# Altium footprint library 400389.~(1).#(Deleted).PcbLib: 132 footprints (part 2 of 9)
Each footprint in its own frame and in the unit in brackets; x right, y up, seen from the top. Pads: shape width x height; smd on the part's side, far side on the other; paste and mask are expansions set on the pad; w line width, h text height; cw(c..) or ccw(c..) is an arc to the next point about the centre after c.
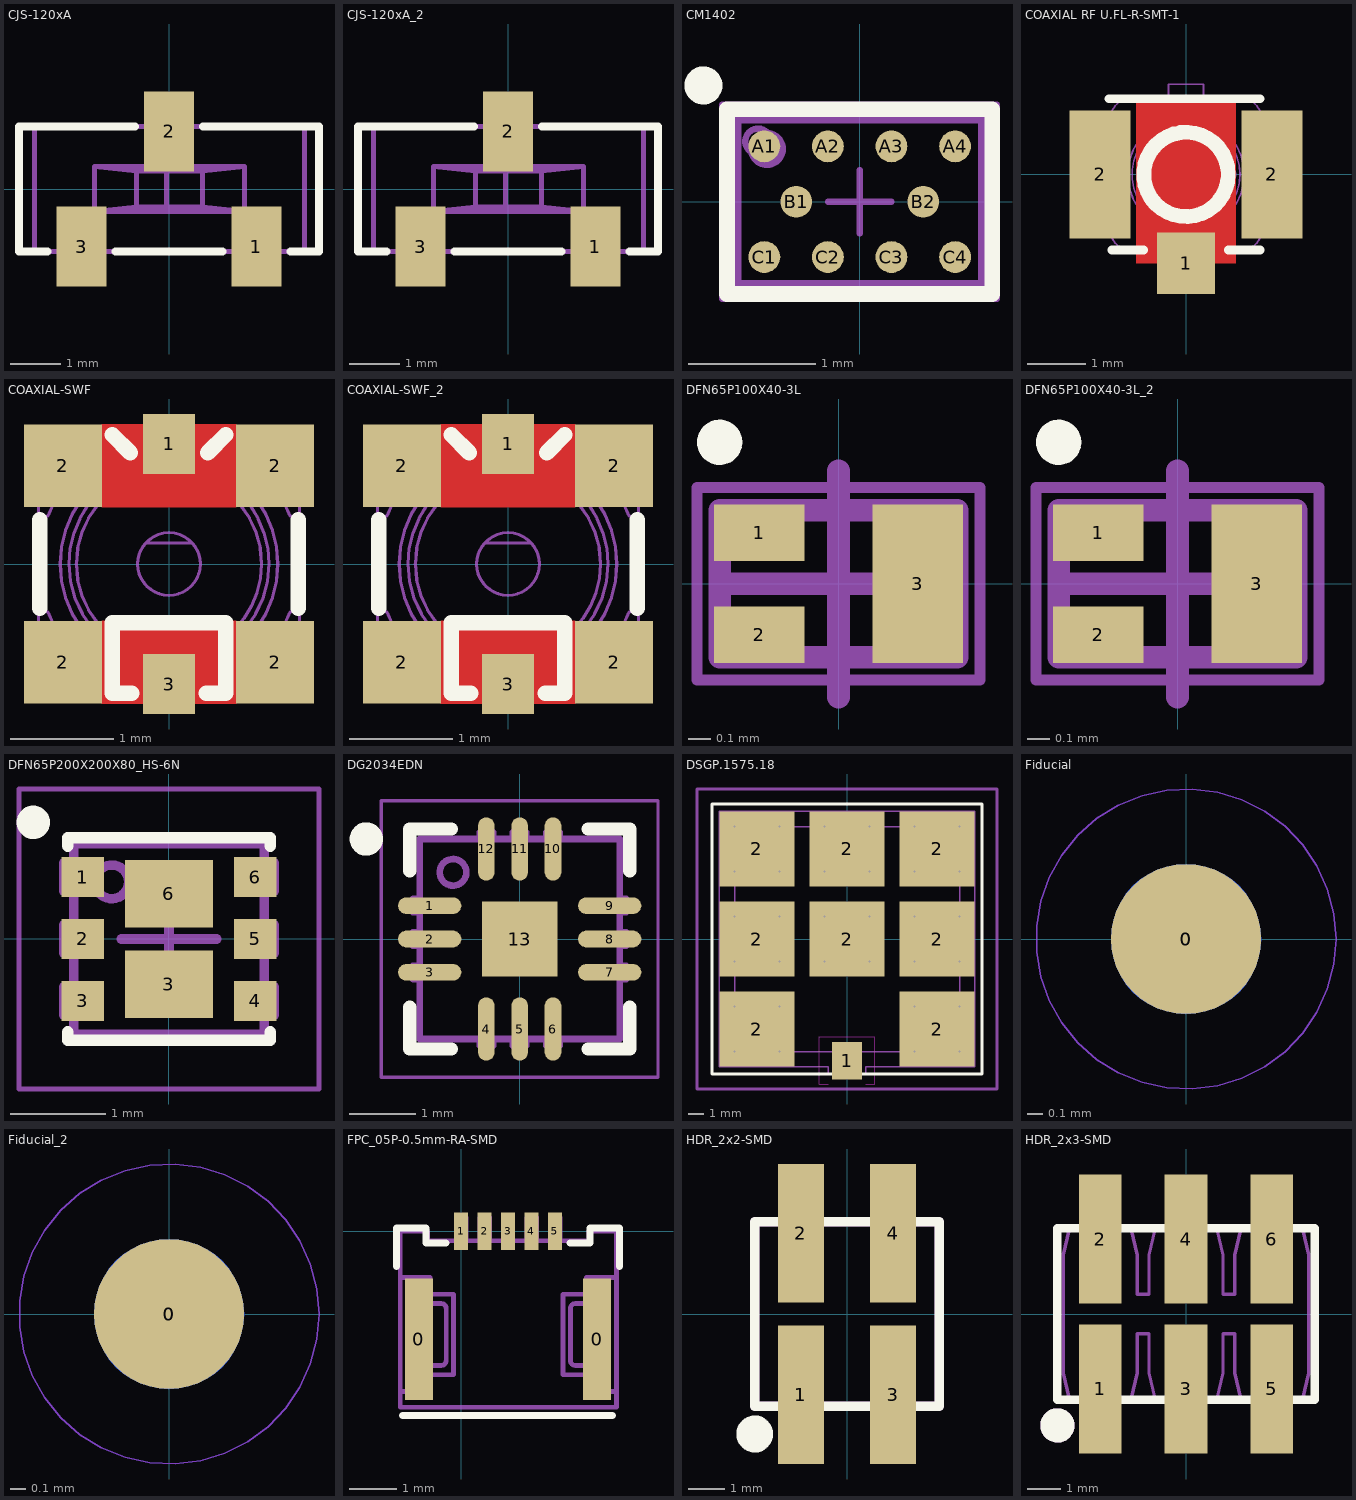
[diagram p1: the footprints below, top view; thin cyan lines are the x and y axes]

## CJS-120xA [mm]
pads (3):
  rect 1x1.6 smd: 1(1.75,-1.15) 2(0,1.15) 3(-1.75,-1.15)
Top Overlay:
  lines w0.152: -2.43,-1.25 -3,-1.25 -3,1.25 -0.68,1.25 ; -1.07,-1.25 1.07,-1.25 ; 0.68,1.25 3,1.25 3,-1.25 2.43,-1.25
Mechanical 7:
  lines w0.1: -2.04,-1.25 -2.04,-1.4 -1.44,-1.4 -1.44,-1.25 ; -0.29,1.25 -0.29,1.4 0.31,1.4 0.31,1.25 ; 0.07,-0.36 -0.65,-0.36 ; 0.07,0.36 -0.65,0.36 ; 1.46,-1.25 1.46,-1.4 2.06,-1.4 2.06,-1.25 ; -1.49,-0.45 -0.65,-0.36 ; -1.49,-0.45 1.51,-0.45 ; -1.49,-0.45 -1.49,0.45 ; -1.49,0.45 -0.65,0.36 ; -1.49,0.45 1.51,0.45 ; -0.65,-0.36 -0.65,0.36 ; 0.67,-0.36 1.51,-0.45 ; 0.67,-0.36 -0.05,-0.36 -0.05,0.36 0.67,0.36 ; 0.67,-0.36 0.67,0.36 ; 0.67,0.36 1.51,0.45 ; 1.51,-0.45 1.51,0.45 ; -2.69,-1.25 2.71,-1.25 2.71,1.25 -2.69,1.25 -2.69,-1.25
  text ".Designator" at -0.775,-1 h0.38
3D body "User Library-CJS-1200TA -Copal Electronics -SPDT Micro Slide Switch.step": height 2.5, standoff 0, extent -3,-1.4 3,1.45

## CJS-120xA_2 [mm]
pads (3):
  rect 1x1.6 smd: 1(1.75,-1.15) 2(0,1.15) 3(-1.75,-1.15)
Top Overlay:
  lines w0.152: -2.43,-1.25 -3,-1.25 -3,1.25 -0.68,1.25 ; -1.07,-1.25 1.07,-1.25 ; 0.68,1.25 3,1.25 3,-1.25 2.43,-1.25
Mechanical 7:
  lines w0.1: -2.04,-1.25 -2.04,-1.4 -1.44,-1.4 -1.44,-1.25 ; -0.29,1.25 -0.29,1.4 0.31,1.4 0.31,1.25 ; 0.07,-0.36 -0.65,-0.36 ; 0.07,0.36 -0.65,0.36 ; 1.46,-1.25 1.46,-1.4 2.06,-1.4 2.06,-1.25 ; -1.49,-0.45 -0.65,-0.36 ; -1.49,-0.45 1.51,-0.45 ; -1.49,-0.45 -1.49,0.45 ; -1.49,0.45 -0.65,0.36 ; -1.49,0.45 1.51,0.45 ; -0.65,-0.36 -0.65,0.36 ; 0.67,-0.36 1.51,-0.45 ; 0.67,-0.36 -0.05,-0.36 -0.05,0.36 0.67,0.36 ; 0.67,-0.36 0.67,0.36 ; 0.67,0.36 1.51,0.45 ; 1.51,-0.45 1.51,0.45 ; -2.69,-1.25 2.71,-1.25 2.71,1.25 -2.69,1.25 -2.69,-1.25
  text ".Designator" at -0.775,-1 h0.38
3D body "User Library-CJS-1200TA -Copal Electronics -SPDT Micro Slide Switch.step": height 2.5, standoff 0, extent -3,-1.4 3,1.45

## CM1402 [mm]
pads (10):
  round 0.25 smd mask+0.05: A1(-0.75,0.435) A2(-0.25,0.435) A3(0.25,0.435) A4(0.75,0.435) B1(-0.5,0) B2(0.5,0) C1(-0.75,-0.435) C2(-0.25,-0.435) C3(0.25,-0.435) C4(0.75,-0.435)
Top Overlay:
  circle w0.2: c-1.23,0.915 r0.05
  lines w0.125: -1.042,-0.727 -1.042,0.727 1.042,0.727 1.042,-0.727 -1.042,-0.727
Mechanical 7:
  circle w0.2: c-0.73,0.415 r0.05
  lines w0.1: -0.98,-0.665 0.98,-0.665 0.98,0.665 -0.98,0.665 -0.98,-0.665
  text ".Designator" at -0.533,-0.127 h0.3
Mechanical 15:
  circle w0.05: c-0.8,0.475 r0.1
  lines w0.05: -0.25,0 0.25,0 ; 0,-0.25 0,0.25 ; -1.08,-0.765 -1.08,0.765 1.08,0.765 1.08,-0.765 -1.08,-0.765
3D body: height 0.72, standoff 0.21, extent -0.98,-0.665 0.98,0.665

## COAXIAL RF U.FL-R-SMT-1 [mm]
pads (3):
  rect 1x1.05 smd: 1(0,-1.525)
  rect 1.05x2.2 smd: 2(-1.475,0) 2(1.475,0)
Top Layer:
  pour cut-out: 0.85,1.3 -0.85,1.3 -0.85,-1.525 0.85,-1.525
Top Overlay:
  circle w0.254: c0,0 r0.725
  lines w0: 0.725,1.3 1.275,1.3
  lines w0.152: -1.325,1.3 1.275,1.3 ; -1.275,-1.3 -0.725,-1.3 ; 0.725,-1.3 1.275,-1.3
Mechanical 7:
  circle w0.03: c0,0 r0.925
  circle w0.03: c0,0 r1
  circle w0.03: c0,0 r0.85
  circle w0.03: c0,0 r0.25
  lines w0.03: -1.3,-0.9 -1.5,-0.9 -1.5,0.9 -1.3,0.9 ; -0.775,-0.346 -0.427,-0.346 ccw(c0,0) 0.427,-0.346 0.775,-0.346 ; -0.775,0.346 -0.427,0.346 cw(c0,0) 0.427,0.346 0.775,0.346 ; -0.3,-1.3 -0.3,-1.55 0.3,-1.55 0.3,-1.3 ; -0.3,0.96 -0.3,1.55 0.3,1.55 0.3,0.96 ; -0.3,1.3 -0.95,1.3 ccw(c-0.95,0.95) -1.3,0.95 -1.3,-0.95 ccw(c-0.95,-0.95) -0.95,-1.3 0.95,-1.3 ccw(c0.95,-0.95) 1.3,-0.95 1.3,0.95 ccw(c0.95,0.95) 0.95,1.3 0.3,1.3 ; 1.3,-0.9 1.5,-0.9 1.5,0.9 1.3,0.9
  text ".Designator" at -0.375,-0.125 h0.38
3D body "U.FL-R-SMT-1.stp": height 1.25, standoff 0, extent -1.5,-1.6 1.5,1.5

## COAXIAL-SWF [mm]
pads (6):
  rect 0.5x0.58 smd: 1(0,1.16) 3(0,-1.16)
  rect 0.75x0.8 smd: 2(-1.025,-0.95) 2(-1.025,0.95) 2(1.025,-0.95) 2(1.025,0.95)
Top Layer:
  pour cut-out: 0.65,-0.55 -0.65,-0.55 -0.65,-1.35 0.65,-1.35
  pour cut-out: -0.65,0.55 0.65,0.55 0.65,1.35 -0.65,1.35
Top Overlay:
  lines w0.15: -1.25,-0.43 -1.25,0.43 ; -0.55,1.25 -0.375,1.075 ; -0.36,-1.25 -0.55,-1.25 -0.55,-0.57 0.55,-0.57 0.55,-1.25 0.36,-1.25 ; 0.375,1.075 0.55,1.25 ; 1.25,-0.43 1.25,0.43
Mechanical 7:
  drawing of 206 lines, arcs and shapes, not listed
  text ".Designator" at -0.785,-0.7 h0.38
3D body: height 1.55, standoff 1.25, extent -1.05,-1.05 1.05,1.05
3D body: height 1.25, standoff 0.95, extent -1.05,-1.049 1.05,1.05
3D body: height 0.9, standoff 0.6, extent -1.05,-1.049 1.05,1.05
3D body: height 0.55, standoff 0.1, extent -1.262,-1.252 1.262,1.253
3D body: height 0.6, standoff 0, extent -1.262,0.655 -0.757,1.248
3D body: height 0.6, standoff 0, extent -1.262,-1.25 -0.757,-0.649
3D body: height 0.6, standoff 0, extent 0.757,-1.246 1.262,-0.653
3D body: height 0.6, standoff 0, extent 0.757,0.655 1.262,1.249
3D body: height 0.95, standoff 0.75, extent -1,-0.999 1,1.001
3D body: height 0.75, standoff 0.6, extent -1.05,-1.049 1.05,1.05
3D body: height 1.4, standoff 0.6, extent -0.9,-0.9 0.9,0.901
3D body: height 0.6, standoff 0.55, extent -1.262,-1.248 1.262,1.251
3D body: height 0.15, standoff 0, extent -0.227,0.899 0.227,1.299
3D body: height 0.15, standoff 0, extent -0.227,-1.301 0.227,-0.758

## COAXIAL-SWF_2 [mm]
pads (6):
  rect 0.5x0.58 smd: 1(0,1.16) 3(0,-1.16)
  rect 0.75x0.8 smd: 2(-1.025,-0.95) 2(-1.025,0.95) 2(1.025,-0.95) 2(1.025,0.95)
Top Layer:
  pour cut-out: -0.65,0.55 0.65,0.55 0.65,1.35 -0.65,1.35
  pour cut-out: 0.65,-0.55 -0.65,-0.55 -0.65,-1.35 0.65,-1.35
Top Overlay:
  lines w0.15: -1.25,-0.43 -1.25,0.43 ; -0.55,1.25 -0.375,1.075 ; -0.36,-1.25 -0.55,-1.25 -0.55,-0.57 0.55,-0.57 0.55,-1.25 0.36,-1.25 ; 0.375,1.075 0.55,1.25 ; 1.25,-0.43 1.25,0.43
Mechanical 7:
  drawing of 206 lines, arcs and shapes, not listed
  text ".Designator" at -0.785,-0.7 h0.38
3D body: height 1.4, standoff 0.6, extent -0.9,-0.9 0.9,0.9
3D body: height 0.75, standoff 0.6, extent -1.05,-1.049 1.05,1.05
3D body: height 0.95, standoff 0.75, extent -1,-0.999 1,1.001
3D body: height 0.6, standoff 0, extent 0.757,0.655 1.262,1.249
3D body: height 0.6, standoff 0, extent 0.757,-1.246 1.262,-0.653
3D body: height 0.6, standoff 0, extent -1.262,-1.25 -0.757,-0.649
3D body: height 0.6, standoff 0, extent -1.262,0.655 -0.757,1.248
3D body: height 0.55, standoff 0.1, extent -1.262,-1.252 1.262,1.253
3D body: height 0.9, standoff 0.6, extent -1.05,-1.049 1.05,1.05
3D body: height 1.25, standoff 0.95, extent -1.05,-1.049 1.05,1.05
3D body: height 1.55, standoff 1.25, extent -1.05,-1.05 1.05,1.05
3D body: height 0.15, standoff 0, extent -0.227,-1.301 0.227,-0.758
3D body: height 0.15, standoff 0, extent -0.227,0.899 0.227,1.299
3D body: height 0.6, standoff 0.55, extent -1.262,-1.248 1.262,1.251

## DFN65P100X40-3L [mm]
pads (3):
  rect 0.4x0.25 smd mask+0.065: 1(-0.35,0.225) 2(-0.35,-0.225)
  rect 0.4x0.7 smd mask+0.065: 3(0.35,0)
Top Overlay:
  circle w0.1: c-0.525,0.625 r0.05
Mechanical 7:
  lines w0.1: -0.525,-0.325 -0.525,0.325 0.525,0.325 0.525,-0.325 -0.525,-0.325
  text ".Designator" at -0.425,-0.175 h0.38
Mechanical 15:
  lines w0.05: -0.625,-0.425 -0.625,0.425 0.625,0.425 0.625,-0.425 -0.625,-0.425
  lines w0.1: -0.5,0 0.5,0 ; 0,-0.5 0,0.5
3D body "DFN65P100X40-3L.step": height 0.4, standoff 0, extent -0.525,-0.325 0.525,0.325

## DFN65P100X40-3L_2 [mm]
pads (3):
  rect 0.4x0.25 smd mask+0.065: 1(-0.35,0.225) 2(-0.35,-0.225)
  rect 0.4x0.7 smd mask+0.065: 3(0.35,0)
Top Overlay:
  circle w0.1: c-0.525,0.625 r0.05
Mechanical 7:
  lines w0.1: -0.525,-0.325 -0.525,0.325 0.525,0.325 0.525,-0.325 -0.525,-0.325
  text ".Designator" at -0.425,-0.175 h0.38
Mechanical 15:
  lines w0.05: -0.625,-0.425 -0.625,0.425 0.625,0.425 0.625,-0.425 -0.625,-0.425
  lines w0.1: -0.5,0 0.5,0 ; 0,-0.5 0,0.5
3D body "DFN65P100X40-3L.step": height 0.4, standoff 0, extent -0.525,-0.325 0.525,0.325

## DFN65P200X200X80_HS-6N [mm]
pads (8):
  rect 0.45x0.42 smd mask+0.055: 1(-0.905,0.65) 2(-0.905,0) 3(-0.905,-0.65) 4(0.905,-0.65) 5(0.905,0) 6(0.905,0.65)
  rect 0.92x0.71 smd mask+0.055: 3(0,-0.475) 6(0,0.475)
Top Overlay:
  circle w0.25: c-1.425,1.225 r0.05
  lines w0.125: -1.063,-0.978 -1.063,-1.063 1.063,-1.063 1.063,-0.978 ; -1.063,0.978 -1.063,1.063 1.063,1.063 1.063,0.978
Mechanical 7:
  circle w0.1: c-0.6,0.6 r0.177
  lines w0.1: -1,-0.8 -1.105,-0.8 -1.105,-0.5 -1,-0.5 ; -1,-0.15 -1.105,-0.15 -1.105,0.15 -1,0.15 ; -1,0.5 -1.105,0.5 -1.105,0.8 -1,0.8 ; 1,-0.8 1.105,-0.8 1.105,-0.5 1,-0.5 ; 1,-0.15 1.105,-0.15 1.105,0.15 1,0.15 ; 1,0.5 1.105,0.5 1.105,0.8 1,0.8 ; -1,-1 1,-1 1,1 -1,1 -1,-1
  text ".Designator" at -0.6,-0.2 h0.38
Mechanical 15:
  lines w0.05: -1.575,-1.575 1.575,-1.575 1.575,1.575 -1.575,1.575 -1.575,-1.575
  lines w0.1: -0.5,0 0.5,0 ; 0,-0.5 0,0.5
3D body "QFN65P200X200X65-6N.step": height 0.65, standoff 0, extent -1.051,-1.05 1.051,1.05

## DG2034EDN [mm]
pads (13):
  oval 0.95x0.25 smd: 1(-1.35,0.5) 2(-1.35,0) 3(-1.35,-0.5) 7(1.35,-0.5) 8(1.35,0) 9(1.35,0.5)
  oval 0.25x0.95 smd: 4(-0.5,-1.35) 5(0,-1.35) 6(0.5,-1.35) 10(0.5,1.35) 11(0,1.35) 12(-0.5,1.35)
  rect 1.13x1.13 smd: 13(0,0)
Top Overlay:
  circle w0.25: c-2.3,1.5 r0.125
  lines w0.2: -1.65,-1.025 -1.65,-1.65 -1.025,-1.65 ; -1.65,1.025 -1.65,1.65 -1.025,1.65 ; 1.025,-1.65 1.65,-1.65 1.65,-1.025 ; 1.025,1.65 1.65,1.65 1.65,1.025
Mechanical 7:
  circle w0.1: c-1,1 r0.2
  lines w0.1: -1.5,-0.6 -1.6,-0.6 -1.6,-0.4 -1.5,-0.4 ; -1.5,-0.1 -1.6,-0.1 -1.6,0.1 -1.5,0.1 ; -1.5,0.4 -1.6,0.4 -1.6,0.6 -1.5,0.6 ; -0.6,-1.5 -0.6,-1.6 -0.4,-1.6 -0.4,-1.5 ; -0.6,1.5 -0.6,1.6 -0.4,1.6 -0.4,1.5 ; -0.1,-1.5 -0.1,-1.6 0.1,-1.6 0.1,-1.5 ; -0.1,1.5 -0.1,1.6 0.1,1.6 0.1,1.5 ; 0.4,-1.5 0.4,-1.6 0.6,-1.6 0.6,-1.5 ; 0.4,1.5 0.4,1.6 0.6,1.6 0.6,1.5 ; 1.5,-0.6 1.6,-0.6 1.6,-0.4 1.5,-0.4 ; 1.5,-0.1 1.6,-0.1 1.6,0.1 1.5,0.1 ; 1.5,0.4 1.6,0.4 1.6,0.6 1.5,0.6 ; -1.5,-1.5 -1.5,1.5 1.5,1.5 1.5,-1.5 -1.5,-1.5
  text ".Designator" at -0.33,-0.152 h0.38
Mechanical 15:
  lines w0.05: -2.075,-2.075 2.075,-2.075 2.075,2.075 -2.075,2.075 -2.075,-2.075
  lines w0.1: -0.5,0 0.5,0 ; 0,-0.5 0,0.5
3D body "DG2034EDN.step": height 1, standoff 0, extent -1.501,-1.501 1.501,1.501

## DSGP.1575.18 [mm]
pads (49):
  rect 2x2.5 smd paste-0.25 mask+0.1: 1(0,-8.1)
  rect 5x5 smd paste-0.6 mask+0.1: 2(-6,-6) 2(-6,0) 2(-6,6) 2(0,0) 2(0,6) 2(6,-6) 2(6,0) 2(6,6)
  round 0.35 on Mech16: 11(-7.5,-7.5) 11(-7.5,-4.5) 11(-7.5,-1.5) 11(-7.5,1.5) 11(-7.5,4.5) 11(-7.5,7.5) 11(-6,-6) 11(-6,0) 11(-6,6) 11(-4.5,-7.5) 11(-4.5,-4.5) 11(-4.5,-1.5) 11(-4.5,1.5) 11(-4.5,4.5) 11(-4.5,7.5) 11(-1.5,-1.5) 11(-1.5,1.5) 11(-1.5,4.5) 11(-1.5,7.5) 11(0,0) 11(0,6) 11(1.5,-1.5) 11(1.5,1.5) 11(1.5,4.5) 11(1.5,7.5) 11(4.5,-7.5) 11(4.5,-4.5) 11(4.5,-1.5) 11(4.5,1.5) 11(4.5,4.5) 11(4.5,7.5) 11(6,-6) 11(6,0) 11(6,6) 11(7.5,-7.5) 11(7.5,-4.5) 11(7.5,-1.5) 11(7.5,1.5) 11(7.5,4.5) 11(7.5,7.5)
via 4.5,-4.5 diameter 0.35 hole 0.15
via 7.5,-4.5 diameter 0.35 hole 0.15
via 6,-6 diameter 0.35 hole 0.15
via 4.5,-7.5 diameter 0.35 hole 0.15
via 7.5,-7.5 diameter 0.35 hole 0.15
via -1.5,1.5 diameter 0.35 hole 0.15
via 1.5,1.5 diameter 0.35 hole 0.15
via 0,0 diameter 0.35 hole 0.15
via -1.5,-1.5 diameter 0.35 hole 0.15
via 1.5,-1.5 diameter 0.35 hole 0.15
via 4.5,1.5 diameter 0.35 hole 0.15
via 7.5,1.5 diameter 0.35 hole 0.15
via 6,0 diameter 0.35 hole 0.15
via 4.5,-1.5 diameter 0.35 hole 0.15
via 7.5,-1.5 diameter 0.35 hole 0.15
via 4.5,7.5 diameter 0.35 hole 0.15
via 7.5,7.5 diameter 0.35 hole 0.15
via 6,6 diameter 0.35 hole 0.15
via 4.5,4.5 diameter 0.35 hole 0.15
via 7.5,4.5 diameter 0.35 hole 0.15
via -1.5,7.5 diameter 0.35 hole 0.15
via 1.5,7.5 diameter 0.35 hole 0.15
via 0,6 diameter 0.35 hole 0.15
via -1.5,4.5 diameter 0.35 hole 0.15
via 1.5,4.5 diameter 0.35 hole 0.15
via -7.5,7.5 diameter 0.35 hole 0.15
via -4.5,7.5 diameter 0.35 hole 0.15
via -6,6 diameter 0.35 hole 0.15
via -7.5,4.5 diameter 0.35 hole 0.15
via -4.5,4.5 diameter 0.35 hole 0.15
via -7.5,1.5 diameter 0.35 hole 0.15
via -4.5,1.5 diameter 0.35 hole 0.15
via -6,0 diameter 0.35 hole 0.15
via -7.5,-1.5 diameter 0.35 hole 0.15
via -4.5,-1.5 diameter 0.35 hole 0.15
via -4.5,-7.5 diameter 0.35 hole 0.15
via -7.5,-7.5 diameter 0.35 hole 0.15
via -6,-6 diameter 0.35 hole 0.15
via -4.5,-4.5 diameter 0.35 hole 0.15
via -7.5,-4.5 diameter 0.35 hole 0.15
Top Overlay:
  lines w0.2: -9,-9 -9,9 9,9 9,-9 -9,-9
Keep-Out Layer:
  lines w0.01: -1.26,-9.69 -1.84,-9.69 -1.84,-6.51 1.84,-6.51 1.84,-9.69 1.26,-9.69
Mechanical 7:
  lines w0.1: -1.25,-9 -1.25,-8.5 -8.5,-8.5 -8.5,8.5 8.5,8.5 8.5,-8.5 1.25,-8.5 1.25,-9 ; -9,-9 9,-9 9,9 -9,9 -9,-9 ; -7.5,-6.5 -7.5,7.5 6.5,7.5 7.5,6.5 7.5,-7.5 -2.25,-7.5 -6.5,-7.5 -7.5,-6.5
  text ".Designator" at -1,-5 h0.38
Mechanical 15:
  lines w0.2: -10,-10 10,-10 10,10 -10,10 -10,-10
Multi-Layer:
  pour cut-out: -2,-6.35 -2,-9.85 2,-9.85 2,-6.35
3D body "DSGP.1575.18.4.A.02.step": height 4.03, standoff -0.02, extent -9,-9 9,9

## Fiducial [mm]
pads (2):
  round 1 smd far side paste+0 mask+0.5: 0(0,0)
  round 1 smd paste+0 mask+0.5: 0(0,0)
Top Layer keep-out:
  circle w0.01: c0,0 r1
Bottom Layer keep-out:
  circle w0.01: c0,0 r1

## Fiducial_2 [mm]
pads (2):
  round 1 smd far side paste+0 mask+0.5: 0(0,0)
  round 1 smd paste+0 mask+0.5: 0(0,0)
Top Layer keep-out:
  circle w0.01: c0,0 r1
Bottom Layer keep-out:
  circle w0.01: c0,0 r1

## FPC_05P-0.5mm-RA-SMD [mm]
pads (7):
  rect 0.6x2.6 smd: 0(-0.9,-2.3) 0(2.9,-2.3)
  rect 0.3x0.8 smd mask+0.05: 1(0,0) 2(0.5,0) 3(1,0) 4(1.5,0) 5(2,0)
Top Overlay:
  lines w0.15: -1.375,-0.75 -1.375,0.075 -0.75,0.075 -0.75,-0.25 -0.325,-0.25 ; -1.25,-3.925 3.225,-3.925 ; 2.325,-0.25 2.75,-0.25 2.75,0.075 3.375,0.075 3.375,-0.75
Mechanical 7:
  lines w0.1: -1.3,-3.416 -0.661,-3.416 -0.661,-3.06 -0.162,-3.06 -0.162,-1.34 -0.661,-1.34 -0.661,-0.983 -1.3,-0.983 ; -1.033,-3.416 -1.033,-0.983 ; -1.027,-2.86 -0.422,-2.86 ccw(c-0.418,-2.762) -0.321,-2.761 -0.321,-1.642 ccw(c-0.418,-1.638) -0.422,-1.54 -1.027,-1.54 ; -0.098,-0.198 -0.098,0.305 0.106,0.305 0.106,-0.198 ; -0.098,-0.048 0.106,-0.048 ; -0.098,0.006 0.106,0.006 ; 0.401,-0.198 0.401,0.305 0.605,0.305 0.605,-0.198 ; 0.401,-0.048 0.605,-0.048 ; 0.401,0.006 0.605,0.006 ; 0.901,-0.198 0.901,0.305 1.104,0.305 1.104,-0.198 ; 0.901,-0.048 1.104,-0.048 ; 0.901,0.006 1.104,0.006 ; 1.406,-0.198 1.406,0.305 1.61,0.305 1.61,-0.198 ; 1.406,-0.048 1.61,-0.048 ; 1.406,0.006 1.61,0.006 ; 1.905,-0.198 1.905,0.305 2.109,0.305 2.109,-0.198 ; 1.905,-0.048 2.109,-0.048 ; 1.905,0.006 2.109,0.006 ; 3.039,-2.86 2.435,-2.86 cw(c2.431,-2.762) 2.333,-2.761 2.333,-1.642 cw(c2.431,-1.638) 2.435,-1.54 3.039,-1.54 ; 3.046,-3.416 3.046,-0.983 ; 3.313,-3.416 2.674,-3.416 2.674,-3.06 2.174,-3.06 2.174,-1.34 2.674,-1.34 2.674,-0.983 3.313,-0.983 ; -1.3,-3.75 -1.3,0.006 -0.712,0.006 -0.712,-0.198 2.724,-0.198 2.724,0.006 3.313,0.006 3.313,-3.75 -1.3,-3.75
  text ".Designator" at 0.55,-2.15 h0.38

## HDR_2x2-SMD [mil]
pads (4):
  rect 50x150 smd: 1(-50,-87.5) 2(-50,87.5) 3(50,-87.5) 4(50,87.5)
Top Overlay:
  circle w20: c-100,-130 r10
  lines w10: -100,-100 100,-100 100,100 -100,100 -100,-100
Mechanical 7:
  lines w10: -100,-100 -100,100 100,100 100,-100 -100,-100
  text ".Designator" at -120,-50 h12.01

## HDR_2x3-SMD [mil]
pads (6):
  rect 50x150 smd: 1(-100,-87.5) 2(-100,87.5) 3(0,-87.5) 4(0,87.5) 5(100,-87.5) 6(100,87.5)
Top Overlay:
  circle w20: c-150,-130 r10
  lines w10: -150,-100 -150,100 150,100 150,-100 -150,-100
Mechanical 7:
  circle w20: c-150,-130 r10
  lines w3.94: -113.78,-98.43 -113.78,-119.75 ccw(c-100,-119.75) -86.22,-119.75 -86.22,-98.43 ; -113.78,98.43 -113.78,119.75 cw(c-100,119.75) -86.22,119.75 -86.22,98.43 ; -13.78,-98.43 -13.78,-119.75 ccw(c0,-119.75) 13.78,-119.75 13.78,-98.43 ; -13.78,98.43 -13.78,119.75 cw(c0,119.75) 13.78,119.75 13.78,98.43 ; 86.22,-98.43 86.22,-119.75 ccw(c100,-119.75) 113.78,-119.75 113.78,-98.43 ; 86.22,98.43 86.22,119.75 cw(c100,119.75) 113.78,119.75 113.78,98.43 ; -143.11,-68.71 -143.11,68.71 -136.22,98.43 -63.78,98.43 -56.89,68.71 -56.89,22.88 -43.11,22.88 -43.11,68.71 -36.22,98.43 36.22,98.43 43.11,68.71 43.11,22.88 56.89,22.88 56.89,68.71 63.78,98.43 136.22,98.43 143.11,68.71 143.11,-68.71 136.22,-98.43 63.78,-98.43 56.89,-68.71 56.89,-22.88 43.11,-22.88 43.11,-68.71 36.22,-98.43 -36.22,-98.43 -43.11,-68.71 -43.11,-22.88 -56.89,-22.88 -56.89,-68.71 -63.78,-98.43 -136.22,-98.43 -143.11,-68.71 ; -111.81,-61.81 -111.81,-38.19 -88.19,-38.19 -88.19,-61.81 -111.81,-61.81 ; -111.81,38.19 -111.81,61.81 -88.19,61.81 -88.19,38.19 -111.81,38.19 ; -11.81,-61.81 11.81,-61.81 11.81,-38.19 -11.81,-38.19 -11.81,-61.81 ; -11.81,38.19 11.81,38.19 11.81,61.81 -11.81,61.81 -11.81,38.19 ; 88.19,-61.81 111.81,-61.81 111.81,-38.19 88.19,-38.19 88.19,-61.81 ; 88.19,38.19 111.81,38.19 111.81,61.81 88.19,61.81 88.19,38.19
  text ".Designator" at -66.93,-15.75 h27
3D body "pin_header_a-sl254-dg-g06mp1.stp": height 382.03, standoff -1.57, extent -149.99,-147.63 150.01,147.64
